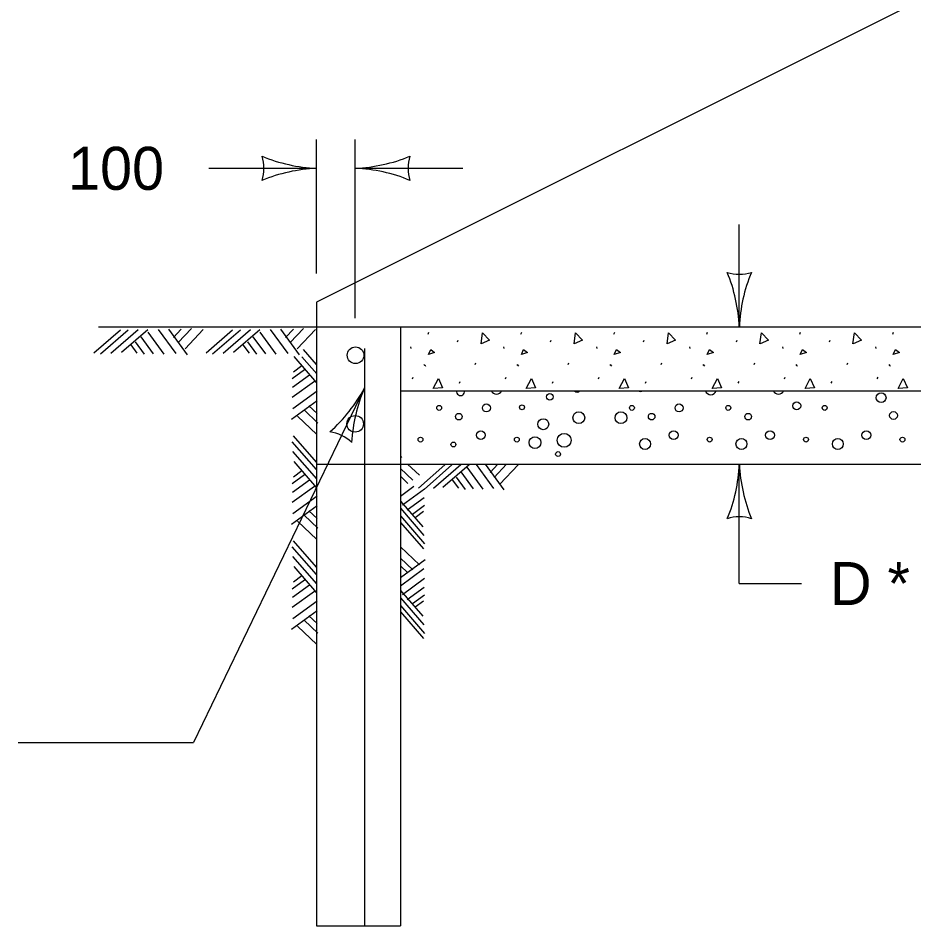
# Model space of a CAD drawing. Extents: x 49991.4 to 50021, y 49987.6 to 50011.4.
# Drawn here: x 50011.775 to 50013.024, y 49989.451 to 49990.718 of the extents above; entities that cross this region are included whole.
import ezdxf

# ---------------------------------------------------------------- set-up
doc = ezdxf.new("R2010")
doc.units = 0
for name, color, linetype in [('Level 1', 7, 'Continuous'), ('Level 2', 7, 'Continuous'), ('Level 3', 7, 'Continuous')]:
    doc.layers.add(name, color=color, linetype=linetype)

msp = doc.modelspace()

# ---------------------------------------------------------------- linework, layer by layer
at = {"layer": 'Level 1'}
for p, q in [((50013.9706, 49991.2116), (50012.1908, 49990.3217)), ((50012.1908, 49990.3217), (50012.1908, 49989.4513)), ((50011.9174, 49990.2827), (50011.8804, 49990.2505)), ((50011.8867, 49990.287), (50012.3078, 49990.287)), ((50011.9283, 49990.2827), (50011.8894, 49990.2488)), ((50011.9421, 49990.2829), (50011.9041, 49990.2498)), ((50011.9553, 49990.2831), (50011.919, 49990.2515)), ((50011.9554, 49990.2797), (50011.978, 49990.2488)), ((50011.9701, 49990.2835), (50011.9946, 49990.2498)), ((50011.9844, 49990.2837), (50012.0104, 49990.248)), ((50011.9914, 49990.2722), (50012.0022, 49990.2837)), ((50011.9979, 49990.2654), (50012.0162, 49990.2847)), ((50012.0074, 49990.2563), (50012.0328, 49990.2833)), ((50012.0738, 49990.2827), (50012.0367, 49990.2505)), ((50012.0847, 49990.2827), (50012.0458, 49990.2488)), ((50012.0985, 49990.2829), (50012.0604, 49990.2498)), ((50012.1117, 49990.2831), (50012.0752, 49990.2515)), ((50012.1117, 49990.2797), (50012.1342, 49990.2488)), ((50012.1263, 49990.2835), (50012.1509, 49990.2498)), ((50012.1406, 49990.2837), (50012.1668, 49990.248)), ((50012.1477, 49990.2722), (50012.1585, 49990.2837)), ((50012.1542, 49990.2654), (50012.1724, 49990.2847)), ((50012.1638, 49990.2563), (50012.1892, 49990.2833)), ((50012.1908, 49990.2827), (50012.1908, 49990.2827)), ((50012.3078, 49990.287), (50012.3078, 49989.4513)), ((50012.3078, 49990.287), (50014.2703, 49990.287)), ((50011.9318, 49990.2621), (50011.9403, 49990.2504)), ((50011.938, 49990.266), (50011.9505, 49990.2488)), ((50011.9458, 49990.2732), (50011.9631, 49990.2494)), ((50012.0882, 49990.2621), (50012.0967, 49990.2504)), ((50012.0944, 49990.266), (50012.1069, 49990.2488)), ((50012.1021, 49990.2732), (50012.1195, 49990.2494)), ((50012.1908, 49990.2344), (50012.1726, 49990.2553)), ((50012.2576, 49990.257), (50012.2576, 49989.4513)), ((50012.1912, 49990.2092), (50012.1596, 49990.2456)), ((50012.191, 49990.2216), (50012.1705, 49990.2451)), ((50012.3078, 49990.2472), (50012.3078, 49990.2472)), ((50012.174, 49990.227), (50012.1569, 49990.2144)), ((50012.1701, 49990.2326), (50012.1585, 49990.2241)), ((50012.1812, 49990.2198), (50012.1574, 49990.2025)), ((50012.1878, 49990.211), (50012.1569, 49990.1885)), ((50012.1915, 49990.1973), (50012.1579, 49990.1727)), ((50012.3078, 49990.1979), (50014.2703, 49990.1979)), ((50012.1918, 49990.1839), (50012.1561, 49990.1579)), ((50012.1803, 49990.1768), (50012.1917, 49990.166)), ((50012.1644, 49990.1623), (50012.1912, 49990.1369)), ((50012.1735, 49990.1711), (50012.1928, 49990.1527)), ((50012.1908, 49990.0879), (50012.1569, 49990.1268)), ((50012.1908, 49990.0982), (50012.1585, 49990.1352)), ((50012.191, 49990.0749), (50012.1579, 49990.113)), ((50012.1912, 49990.0627), (50012.1596, 49990.0991)), ((50012.1701, 49990.0861), (50012.1585, 49990.0776)), ((50012.1908, 49990.0955), (50014.2703, 49990.0955)), ((50012.325, 49990.0731), (50012.3078, 49990.0894)), ((50012.3342, 49990.0801), (50012.3179, 49990.0955)), ((50012.3698, 49990.0944), (50012.3328, 49990.0621)), ((50012.3796, 49990.0944), (50012.3407, 49990.0604)), ((50012.3919, 49990.0945), (50012.3538, 49990.0614)), ((50012.4035, 49990.0948), (50012.3671, 49990.063)), ((50012.3921, 49990.0848), (50012.4094, 49990.061)), ((50012.4004, 49990.0914), (50012.4229, 49990.0605)), ((50012.4133, 49990.0951), (50012.4378, 49990.0615)), ((50012.4259, 49990.0953), (50012.452, 49990.0597)), ((50012.433, 49990.0839), (50012.4438, 49990.0953)), ((50012.4384, 49990.077), (50012.4559, 49990.0955)), ((50012.4465, 49990.0678), (50012.472, 49990.0948)), ((50012.174, 49990.0805), (50012.1569, 49990.0679)), ((50012.1812, 49990.0733), (50012.1574, 49990.056)), ((50012.3182, 49990.0687), (50012.3078, 49990.0786)), ((50012.3801, 49990.0737), (50012.3886, 49990.0621)), ((50012.3855, 49990.0776), (50012.398, 49990.0604)), ((50012.1878, 49990.0644), (50012.1569, 49990.0418)), ((50012.3078, 49990.0508), (50012.3267, 49990.0646)), ((50012.3108, 49990.0388), (50012.3416, 49990.0613)), ((50012.1915, 49990.0507), (50012.1579, 49990.0262)), ((50012.3174, 49990.0316), (50012.3411, 49990.0489)), ((50012.1918, 49990.0374), (50012.1561, 49990.0113)), ((50012.3078, 49990.044), (50012.339, 49990.0082)), ((50012.3246, 49990.0259), (50012.3416, 49990.0383)), ((50012.1735, 49990.0244), (50012.1928, 49990.0062)), ((50012.1803, 49990.0303), (50012.1917, 49990.0195)), ((50012.3078, 49990.034), (50012.3406, 49989.9962)), ((50012.3078, 49990.0232), (50012.3416, 49989.9845)), ((50012.3284, 49990.0213), (50012.34, 49990.0298)), ((50012.1644, 49990.0158), (50012.1912, 49989.9903)), ((50012.3078, 49990.0143), (50012.34, 49989.9774)), ((50012.1908, 49989.9517), (50012.1585, 49989.9887)), ((50012.1908, 49989.9414), (50012.1569, 49989.9803)), ((50012.3342, 49989.9551), (50012.3078, 49989.98)), ((50012.191, 49989.9284), (50012.1579, 49989.9665)), ((50012.325, 49989.9482), (50012.3078, 49989.9645)), ((50012.3078, 49989.9374), (50012.3424, 49989.9626)), ((50012.1912, 49989.9162), (50012.1596, 49989.9525)), ((50012.3182, 49989.9438), (50012.3078, 49989.9537)), ((50012.3078, 49989.9259), (50012.3406, 49989.9499)), ((50012.174, 49989.9338), (50012.1569, 49989.9213)), ((50012.1701, 49989.9396), (50012.1585, 49989.9311)), ((50012.3108, 49989.9138), (50012.3416, 49989.9363)), ((50012.1812, 49989.9267), (50012.1574, 49989.9093)), ((50012.3174, 49989.9066), (50012.3411, 49989.924)), ((50012.1878, 49989.9179), (50012.1569, 49989.8953)), ((50012.3078, 49989.9191), (50012.339, 49989.8832)), ((50012.3078, 49989.9089), (50012.3406, 49989.8712)), ((50012.3246, 49989.9009), (50012.3416, 49989.9134)), ((50012.1915, 49989.9042), (50012.1579, 49989.8797)), ((50012.3078, 49989.8983), (50012.3416, 49989.8594)), ((50012.3284, 49989.8964), (50012.34, 49989.9049)), ((50012.1918, 49989.8909), (50012.1561, 49989.8648)), ((50012.1803, 49989.8838), (50012.1917, 49989.873)), ((50012.3078, 49989.8894), (50012.34, 49989.8523)), ((50012.1735, 49989.8779), (50012.1928, 49989.8597)), ((50012.1644, 49989.8693), (50012.1912, 49989.8437)), ((50012.1908, 49989.6899), (50012.1908, 49989.6899)), ((50012.1908, 49989.4513), (50012.3078, 49989.4513))]:
    msp.add_line(p, q, dxfattribs=at)
for centre, radius in [((50012.2452, 49990.2475), 0.0116), ((50012.5162, 49990.1895), 0.0046), ((50012.9783, 49990.1882), 0.00684), ((50012.3618, 49990.174), 0.00341), ((50012.4277, 49990.174), 0.00552), ((50012.4774, 49990.1749), 0.00341), ((50012.6307, 49990.174), 0.00341), ((50012.6965, 49990.174), 0.00552), ((50012.7651, 49990.174), 0.00341), ((50012.8606, 49990.1769), 0.00552), ((50012.8996, 49990.174), 0.00341), ((50012.2447, 49990.1518), 0.0116), ((50012.3894, 49990.1618), 0.0046), ((50012.5566, 49990.1603), 0.00824), ((50012.6154, 49990.1603), 0.00824), ((50012.6582, 49990.1618), 0.0046), ((50012.7927, 49990.1618), 0.0046), ((50012.9955, 49990.1634), 0.00552), ((50012.507, 49990.1513), 0.00766), ((50012.42, 49990.1359), 0.00613), ((50012.5363, 49990.1288), 0.00968), ((50012.6889, 49990.1359), 0.00613), ((50012.8233, 49990.1359), 0.00613), ((50012.9577, 49990.1359), 0.00613), ((50012.3358, 49990.1298), 0.00341), ((50012.3817, 49990.123), 0.00341), ((50012.4702, 49990.1298), 0.00341), ((50012.4955, 49990.1256), 0.00824), ((50012.6491, 49990.1237), 0.00766), ((50012.7391, 49990.1298), 0.00341), ((50012.7835, 49990.1237), 0.00766), ((50012.8735, 49990.1298), 0.00341), ((50012.9179, 49990.1237), 0.00766), ((50013.008, 49990.1298), 0.00341), ((50012.5277, 49990.1096), 0.00341)]:
    msp.add_circle(centre, radius, dxfattribs=at)
for centre, radius, start, end in [((50012.3917, 49990.1968), 0.00552, 168.5096, 11.4904), ((50012.4418, 49990.2009), 0.00765, 202.8197, 337.1803), ((50012.5545, 49990.2017), 0.00552, 222.7241, 317.2759), ((50012.6428, 49990.2038), 0.00684, 238.3741, 301.6259), ((50012.7407, 49990.2), 0.00765, 195.3909, 344.6091), ((50012.8351, 49990.2009), 0.00765, 202.8197, 337.1803), ((50012.3024, 49990.1023), 0.00765, 14.7763, 45.1363)]:
    msp.add_arc(centre, radius, start, end, dxfattribs=at)
at = {"layer": 'Level 3'}
for p, q in [((50012.1908, 49990.3617), (50012.1908, 49990.5483)), ((50012.2449, 49990.2991), (50012.2449, 49990.5483)), ((50012.0408, 49990.5083), (50012.1908, 49990.5083)), ((50012.2449, 49990.5083), (50012.3949, 49990.5083)), ((50012.7805, 49990.287), (50012.7805, 49990.4299)), ((50012.3463, 49990.2771), (50012.3474, 49990.2796)), ((50012.4759, 49990.2771), (50012.477, 49990.2796)), ((50012.6056, 49990.2771), (50012.6067, 49990.2796)), ((50012.7353, 49990.2771), (50012.7363, 49990.2796)), ((50012.8649, 49990.2771), (50012.866, 49990.2796)), ((50012.9946, 49990.2771), (50012.9957, 49990.2796)), ((50012.3874, 49990.266), (50012.3885, 49990.2685)), ((50012.5171, 49990.266), (50012.5182, 49990.2685)), ((50012.6467, 49990.266), (50012.6478, 49990.2685)), ((50012.7764, 49990.266), (50012.7775, 49990.2685)), ((50012.9061, 49990.266), (50012.9071, 49990.2685)), ((50012.3221, 49990.2592), (50012.3224, 49990.2568)), ((50012.4518, 49990.2592), (50012.4521, 49990.2568)), ((50012.5814, 49990.2592), (50012.5817, 49990.2568)), ((50012.7111, 49990.2592), (50012.7114, 49990.2568)), ((50012.8408, 49990.2592), (50012.841, 49990.2568)), ((50012.9704, 49990.2592), (50012.9707, 49990.2568)), ((50012.4121, 49990.2346), (50012.4131, 49990.2371)), ((50012.5417, 49990.2346), (50012.5428, 49990.2371)), ((50012.6714, 49990.2346), (50012.6725, 49990.2371)), ((50012.801, 49990.2346), (50012.8021, 49990.2371)), ((50012.9307, 49990.2346), (50012.9318, 49990.2371)), ((50012.3406, 49990.2346), (50012.3417, 49990.233)), ((50012.3417, 49990.234), (50012.3428, 49990.2324)), ((50012.4703, 49990.2346), (50012.4713, 49990.233)), ((50012.4713, 49990.234), (50012.4724, 49990.2324)), ((50012.5999, 49990.2346), (50012.601, 49990.233)), ((50012.601, 49990.234), (50012.6021, 49990.2324)), ((50012.7296, 49990.2346), (50012.7307, 49990.233)), ((50012.7307, 49990.234), (50012.7317, 49990.2324)), ((50012.8592, 49990.2346), (50012.8603, 49990.233)), ((50012.8603, 49990.234), (50012.8614, 49990.2324)), ((50012.9889, 49990.2346), (50012.99, 49990.233)), ((50012.99, 49990.234), (50012.991, 49990.2324)), ((50012.3246, 49990.2146), (50012.3257, 49990.217)), ((50012.4543, 49990.2146), (50012.4554, 49990.217)), ((50012.5839, 49990.2146), (50012.585, 49990.217)), ((50012.7136, 49990.2146), (50012.7147, 49990.217)), ((50012.8433, 49990.2146), (50012.8443, 49990.217)), ((50012.9729, 49990.2146), (50012.974, 49990.217)), ((50012.2576, 49990.2018), (50012.0194, 49989.7071)), ((50012.3901, 49990.2084), (50012.3912, 49990.2108)), ((50012.5198, 49990.2084), (50012.5209, 49990.2108)), ((50012.6495, 49990.2084), (50012.6505, 49990.2108)), ((50012.7791, 49990.2084), (50012.7802, 49990.2108)), ((50012.9088, 49990.2084), (50012.9098, 49990.2108)), ((50012.7805, 49989.929), (50012.7805, 49990.0955)), ((50012.7805, 49989.929), (50012.867, 49989.929)), ((50011.7746, 49989.7071), (50012.0194, 49989.7071))]:
    msp.add_line(p, q, dxfattribs=at)
for points in [[(50012.4204, 49990.2632), (50012.4225, 49990.2787), (50012.4322, 49990.2687), (50012.4206, 49990.2633)], [(50012.55, 49990.2632), (50012.5522, 49990.2787), (50012.5619, 49990.2687), (50012.5503, 49990.2633)], [(50012.6797, 49990.2632), (50012.6818, 49990.2787), (50012.6915, 49990.2687), (50012.6799, 49990.2633)], [(50012.8093, 49990.2632), (50012.8115, 49990.2787), (50012.8212, 49990.2687), (50012.8096, 49990.2633)], [(50012.939, 49990.2632), (50012.9411, 49990.2787), (50012.9508, 49990.2687), (50012.9392, 49990.2633)], [(50012.3468, 49990.2487), (50012.3501, 49990.2555), (50012.3555, 49990.2514), (50012.3468, 49990.2487)], [(50012.4765, 49990.2487), (50012.4797, 49990.2555), (50012.4852, 49990.2514), (50012.4765, 49990.2487)], [(50012.6061, 49990.2487), (50012.6094, 49990.2555), (50012.6148, 49990.2514), (50012.6061, 49990.2487)], [(50012.7358, 49990.2487), (50012.739, 49990.2555), (50012.7445, 49990.2514), (50012.7358, 49990.2487)], [(50012.8655, 49990.2487), (50012.8687, 49990.2555), (50012.8741, 49990.2514), (50012.8655, 49990.2487)], [(50012.9951, 49990.2487), (50012.9984, 49990.2555), (50013.0038, 49990.2514), (50012.9951, 49990.2487)], [(50012.3536, 49990.2011), (50012.3609, 49990.2149), (50012.3666, 49990.2021), (50012.3539, 49990.2011)], [(50012.4833, 49990.2011), (50012.4906, 49990.2149), (50012.4963, 49990.2021), (50012.4835, 49990.2011)], [(50012.6129, 49990.2011), (50012.6202, 49990.2149), (50012.6259, 49990.2021), (50012.6132, 49990.2011)], [(50012.7426, 49990.2011), (50012.7499, 49990.2149), (50012.7556, 49990.2021), (50012.7428, 49990.2011)], [(50012.8722, 49990.2011), (50012.8795, 49990.2149), (50012.8852, 49990.2021), (50012.8725, 49990.2011)], [(50013.0019, 49990.2011), (50013.0092, 49990.2149), (50013.0149, 49990.2021), (50013.0021, 49990.2011)]]:
    msp.add_lwpolyline(points, dxfattribs=at)
for centre, radius, start, end in [((50012.2, 49990.7305), 0.2223, 247.456, 267.6395), ((50012.0626, 49990.5083), 0.0548, 342.1388, 17.8612), ((50012.2335, 49990.741), 0.233, 272.8273, 292.0772), ((50012.3732, 49990.5083), 0.0548, 162.1388, 197.8612), ((50012.2023, 49990.2756), 0.233, 92.8273, 112.0772), ((50012.2358, 49990.2862), 0.2223, 67.456, 87.6395), ((50012.7805, 49990.4152), 0.0548, 252.1388, 287.8612), ((50012.5478, 49990.2755), 0.233, 2.8273, 22.0772), ((50013.0027, 49990.2779), 0.2223, 157.456, 177.6395), ((50012.0615, 49990.3065), 0.2223, 311.7444, 331.9279), ((50012.4723, 49990.1112), 0.233, 157.1157, 176.3655), ((50012.202, 49990.0863), 0.0548, 46.4272, 82.1495), ((50012.5584, 49990.1047), 0.2223, 337.456, 357.6395), ((50013.0133, 49990.107), 0.233, 182.8273, 202.0772), ((50012.7805, 49989.9673), 0.0548, 72.1388, 107.8612)]:
    msp.add_arc(centre, radius, start, end, dxfattribs=at)

# ---------------------------------------------------------------- texts
at = {"layer": 'Level 2'}
for s, p in [('100', (50011.8443, 49990.4783)), ('D *', (50012.907, 49989.899))]:
    msp.add_text(s, height=0.06, dxfattribs=at).set_placement(p)

doc.saveas('drawing.dxf')
